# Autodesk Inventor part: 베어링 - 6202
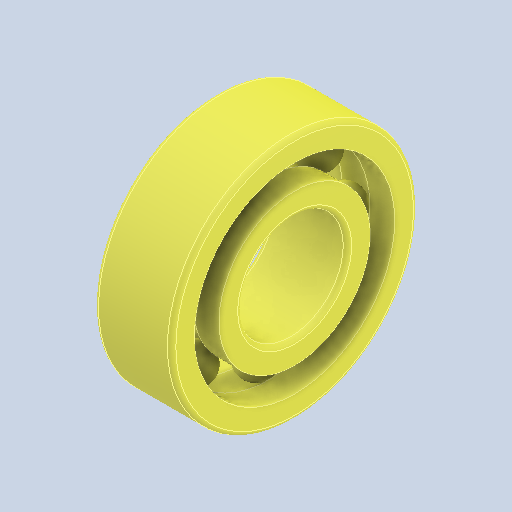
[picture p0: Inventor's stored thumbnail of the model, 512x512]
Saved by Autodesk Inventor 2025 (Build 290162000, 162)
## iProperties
Created: 2024-07
Part Number: 베어링 - 6202
Material: 강, 연강
Description: 깊은 그루브 볼 베어링
Document SubType Name: Modeling
Designer: deana
Density: 7.86 g/cm^3
Appearance: 기본값
Author: jhkim
Sending System: Autodesk Inventor 2025
Preprocessor: ST-DEVELOPER v20
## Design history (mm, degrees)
feature "Solid1"
feature "Solid1:1"
feature "Solid1:2"
feature "Solid1:3"
feature "Solid1:4"
feature "Solid1:5"
feature "Solid1:6"
feature "Solid1:7"
feature "Solid1:8"
feature "Solid1:9"
node "솔리드1"
node "솔리드2"
node "솔리드3"
node "솔리드4"
node "솔리드5"
node "솔리드6"
node "솔리드7"
node "솔리드8"
node "솔리드9"
node "솔리드10"
